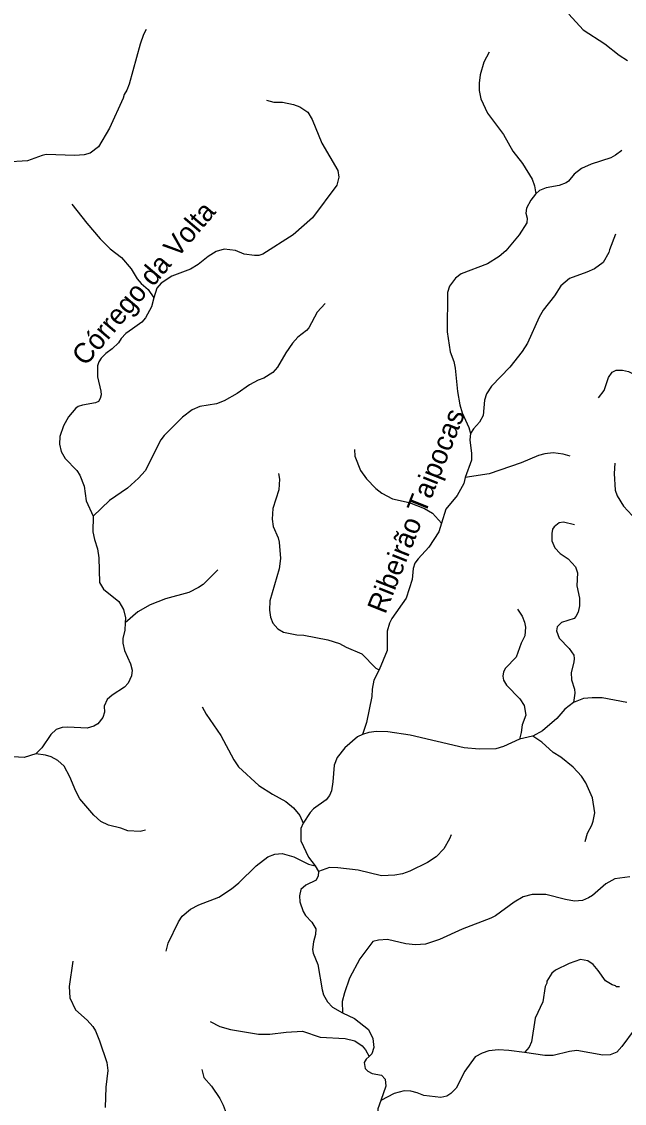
# Model space of a CAD drawing. Extents: x 500 to 555.2, y 9115.7 to 9171.
# Drawn here: x 544.2 to 549, y 9135.74 to 9144.36 of the extents above; entities that cross this region are included whole.
import ezdxf
from ezdxf.enums import TextEntityAlignment as Align

# ---------------------------------------------------------------- set-up
doc = ezdxf.new("R2010")
doc.units = 0
doc.header["$LTSCALE"] = 0.064
doc.layers.add('61', color=7, linetype='Continuous')
doc.layers.add('7', color=7, linetype='Continuous', lineweight=25)

msp = doc.modelspace()

# ---------------------------------------------------------------- linework, layer by layer
at = {"layer": '7'}
for points in [[(548.5564, 9144.4223), (548.6691, 9144.2983), (548.8429, 9144.1866), (548.9572, 9144.0957), (549.0224, 9144.0519)], [(545.189, 9144.3008), (545.1685, 9144.2602), (545.1419, 9144.1825), (545.0528, 9143.8636), (545.0338, 9143.8164), (545.0126, 9143.7827), (545.0063, 9143.7519), (544.8974, 9143.514), (544.8082, 9143.3648), (544.7427, 9143.3133), (544.6949, 9143.3013), (544.6201, 9143.2948), (544.3931, 9143.303), (544.3598, 9143.2963), (544.2439, 9143.2531), (544.0717, 9143.2422)], [(547.9205, 9144.1193), (547.8792, 9144.039), (547.8506, 9143.9389), (547.8421, 9143.8721), (547.8421, 9143.8125), (547.8553, 9143.7469), (547.908, 9143.6337), (548.0355, 9143.4636), (548.1114, 9143.3303), (548.186, 9143.233), (548.2652, 9143.106), (548.2829, 9143.0533), (548.2921, 9142.9904)], [(546.1464, 9143.7355), (546.2072, 9143.7212), (546.2755, 9143.7195), (546.3636, 9143.7032), (546.4138, 9143.6831), (546.4777, 9143.6404), (546.512, 9143.5826), (546.589, 9143.3944), (546.7167, 9143.1749), (546.7244, 9143.1241), (546.7075, 9143.0601), (546.5146, 9142.7989), (546.3595, 9142.6636), (546.1181, 9142.5091), (546.0879, 9142.5), (546.0515, 9142.4977), (545.9686, 9142.5103), (545.8999, 9142.5379), (545.8104, 9142.55), (545.7468, 9142.5299), (545.6839, 9142.4897), (545.6036, 9142.427), (545.5433, 9142.3891), (545.3925, 9142.3348), (545.3089, 9142.2787), (545.2745, 9142.2387), (545.2514, 9142.1606)], [(548.9786, 9143.3359), (548.9286, 9143.2976), (548.8912, 9143.2772), (548.7338, 9143.2277), (548.6578, 9143.1932), (548.5974, 9143.148), (548.5526, 9143.0918), (548.5337, 9143.0781), (548.4795, 9143.0567), (548.3757, 9143.0389), (548.3222, 9143.0154), (548.2921, 9142.9904)], [(548.2921, 9142.9904), (548.29, 9142.9887), (548.2522, 9142.9404), (548.2195, 9142.8754), (548.2128, 9142.836), (548.2241, 9142.796), (548.2208, 9142.759), (548.1602, 9142.6626), (548.0552, 9142.5353), (548, 9142.4897), (547.9082, 9142.4323), (547.6981, 9142.3523), (547.6524, 9142.3177), (547.6046, 9142.2553), (547.5896, 9142.203), (547.5858, 9141.8898), (547.6121, 9141.7313), (547.6395, 9141.6535), (547.6515, 9141.6), (547.6698, 9141.4149), (547.6884, 9141.3075), (547.7068, 9141.246), (547.759, 9141.1286), (547.7738, 9141.0809)], [(544.5978, 9142.9089), (544.7152, 9142.7564), (544.8221, 9142.6304), (544.9016, 9142.551), (544.9917, 9142.4823), (545.0704, 9142.3927), (545.1183, 9142.3127), (545.1492, 9142.2757), (545.2044, 9142.2268), (545.2514, 9142.1606)], [(548.9291, 9142.6689), (548.8789, 9142.544), (548.8751, 9142.5233), (548.83, 9142.4441), (548.7616, 9142.3924), (548.6999, 9142.3647), (548.5621, 9142.3154), (548.4924, 9142.2574), (548.4423, 9142.1777), (548.3524, 9142.0626), (548.3212, 9142.0076), (548.2273, 9141.8008), (548.1856, 9141.7343), (548.0864, 9141.6086), (547.9393, 9141.458), (547.8998, 9141.3973), (547.8846, 9141.3454), (547.8731, 9141.2238), (547.8449, 9141.1701), (547.7964, 9141.1167), (547.7738, 9141.0809)], [(545.2514, 9142.1606), (545.2305, 9142.0897), (545.1847, 9142.001), (545.1551, 9141.9681), (545.0793, 9141.9153), (545.0262, 9141.8781), (544.9895, 9141.8369), (544.9678, 9141.8033), (544.9178, 9141.755), (544.8671, 9141.719), (544.8293, 9141.6795), (544.8127, 9141.6517), (544.8022, 9141.619), (544.8012, 9141.5324), (544.8287, 9141.4182), (544.8303, 9141.3888), (544.8233, 9141.3588), (544.8091, 9141.3354), (544.7865, 9141.3244), (544.6806, 9141.3064), (544.6477, 9141.2955), (544.6276, 9141.2808), (544.5712, 9141.212), (544.5309, 9141.1401), (544.5014, 9141.0567), (544.4992, 9140.9951), (544.5108, 9140.9356), (544.5434, 9140.8818), (544.6359, 9140.7862), (544.6598, 9140.749), (544.694, 9140.6611), (544.7105, 9140.543), (544.768, 9140.4223), (544.768, 9140.4205)], [(546.6153, 9142.1156), (546.5519, 9142.0459), (546.4862, 9141.9224), (546.467, 9141.9002), (546.3974, 9141.8483), (546.3555, 9141.8004), (546.3005, 9141.722), (546.2364, 9141.6089), (546.1976, 9141.5651), (546.1262, 9141.5216), (546.0805, 9141.5044), (546.0119, 9141.4677), (545.9134, 9141.3988), (545.8117, 9141.3405), (545.75, 9141.3164), (545.6175, 9141.2961), (545.5566, 9141.2701), (545.4789, 9141.2116), (545.3312, 9141.0644), (545.3054, 9141.0307), (545.1804, 9140.7839), (545.1278, 9140.7233), (545.0415, 9140.6452), (544.8973, 9140.5468), (544.768, 9140.4205)], [(548.7933, 9141.3636), (548.8368, 9141.423), (548.8724, 9141.5271), (548.9023, 9141.5694), (548.9324, 9141.5836), (548.9842, 9141.5836), (549.0312, 9141.5738), (549.1401, 9141.5213), (549.1892, 9141.5032), (549.238, 9141.474), (549.3757, 9141.4132), (549.4713, 9141.35), (549.5639, 9141.3059), (549.8091, 9141.2538), (549.864, 9141.225), (549.9093, 9141.1821)], [(547.7738, 9141.0809), (547.7682, 9141.0296), (547.7812, 9140.921), (547.7813, 9140.8678), (547.7316, 9140.7287)], [(546.8493, 9140.9539), (546.8514, 9140.8994), (546.8953, 9140.7857), (546.9444, 9140.7199), (547.0181, 9140.6409), (547.0672, 9140.6034), (547.1509, 9140.5607), (547.2853, 9140.5292), (547.4068, 9140.4835), (547.4714, 9140.4446), (547.5424, 9140.3656)], [(548.5671, 9140.8991), (548.5102, 9140.9162), (548.4321, 9140.926), (548.3647, 9140.9178), (548.3139, 9140.9051), (548.1761, 9140.8456), (547.9225, 9140.7591), (547.7316, 9140.7287)], [(548.9218, 9140.8426), (548.9181, 9140.7609), (548.9266, 9140.6297), (548.9425, 9140.5823), (548.9922, 9140.5014), (549.0611, 9140.427), (549.1211, 9140.3318), (549.161, 9140.285), (549.2336, 9140.2502), (549.4433, 9140.2095), (549.612, 9140.2223), (549.6545, 9140.2159), (549.6966, 9140.1965), (549.718, 9140.1735), (549.7331, 9140.1163)], [(546.2439, 9140.7613), (546.2509, 9140.7168), (546.2461, 9140.6322), (546.1983, 9140.4826), (546.1936, 9140.3985), (546.2002, 9140.3395), (546.2408, 9140.2476), (546.249, 9140.2148), (546.2591, 9140.083), (546.249, 9140.0005), (546.1756, 9139.7479), (546.1723, 9139.6725), (546.1803, 9139.6178), (546.1993, 9139.5696), (546.2391, 9139.5231), (546.2833, 9139.4972), (546.3886, 9139.4766), (546.4455, 9139.4728), (546.6358, 9139.4369), (546.7287, 9139.4069), (546.7812, 9139.3774), (546.9064, 9139.3245), (547.0175, 9139.2114), (547.0459, 9139.1959)], [(547.7316, 9140.7287), (547.7199, 9140.6823), (547.6669, 9140.5855), (547.5773, 9140.477), (547.5424, 9140.3656)], [(544.768, 9140.4205), (544.7655, 9140.2958), (544.7762, 9140.2346), (544.8009, 9140.1617), (544.8123, 9140.0896), (544.8174, 9139.8919), (544.8482, 9139.8409), (544.9714, 9139.7401), (545.0097, 9139.6778), (545.0236, 9139.6123), (545.0217, 9139.5703)], [(547.5424, 9140.3656), (547.521, 9140.2974), (547.4397, 9140.1744), (547.3553, 9140.0818), (547.3307, 9140.0458), (547.3151, 9140.005), (547.3089, 9139.9158), (547.2612, 9139.7682), (547.147, 9139.6046), (547.1279, 9139.5697), (547.1088, 9139.505), (547.1087, 9139.3515), (547.0459, 9139.1959)], [(548.6011, 9140.3533), (548.5135, 9140.3748), (548.4779, 9140.3672), (548.4386, 9140.3364), (548.4272, 9140.3179), (548.4195, 9140.2831), (548.4214, 9140.2253), (548.446, 9140.1678), (548.4881, 9140.1241), (548.5505, 9140.0811), (548.6081, 9140.0183), (548.6261, 9139.9702), (548.6212, 9139.8665), (548.6409, 9139.7673), (548.6408, 9139.7057), (548.6295, 9139.6571), (548.6125, 9139.6216), (548.5989, 9139.607), (548.4967, 9139.5743), (548.464, 9139.5403), (548.4571, 9139.507), (548.4788, 9139.4499), (548.5601, 9139.3667), (548.5952, 9139.3133), (548.5984, 9139.2859), (548.5965, 9139.257), (548.5737, 9139.1743), (548.5766, 9139.1178), (548.6013, 9139.0431), (548.6047, 9139.0109), (548.5924, 9138.9376)], [(545.7592, 9139.9928), (545.6431, 9139.8771), (545.6071, 9139.8516), (545.5303, 9139.814), (545.3424, 9139.7631), (545.2208, 9139.7145), (545.1228, 9139.6589), (545.0217, 9139.5703)], [(548.1463, 9139.6815), (548.1845, 9139.6243), (548.2042, 9139.5757), (548.2111, 9139.5376), (548.2059, 9139.469), (548.1763, 9139.4093), (548.1365, 9139.299), (548.052, 9139.2104), (548.0361, 9139.182), (548.0292, 9139.146), (548.0346, 9139.1139), (548.0604, 9139.0746), (548.1667, 9138.966), (548.2002, 9138.9115), (548.2127, 9138.8366), (548.1833, 9138.7586), (548.1768, 9138.6964), (548.1622, 9138.6455)], [(545.0217, 9139.5703), (545.019, 9139.5127), (545.0044, 9139.4463), (545.0044, 9139.4099), (545.0173, 9139.352), (545.0647, 9139.2438), (545.0765, 9139.1934), (545.0715, 9139.1481), (545.0456, 9139.0896), (545.0162, 9139.0583), (544.9195, 9138.9959), (544.8797, 9138.961), (544.8554, 9138.9067), (544.8566, 9138.8595), (544.8438, 9138.8174), (544.8048, 9138.7677), (544.7725, 9138.7477), (544.7178, 9138.7331), (544.5663, 9138.7412), (544.5205, 9138.7378), (544.4711, 9138.7203), (544.4286, 9138.6812), (544.3567, 9138.5762), (544.3112, 9138.5267), (544.3105, 9138.5265)], [(547.0459, 9139.1959), (547.0016, 9139.1142), (546.989, 9139.0425), (546.9857, 9138.9834), (546.9431, 9138.7773), (546.913, 9138.6824)], [(548.5924, 9138.9376), (548.5247, 9138.8842), (548.4609, 9138.809), (548.3475, 9138.7109), (548.2685, 9138.6684)], [(549.0185, 9138.9355), (549.0183, 9138.9355), (548.8206, 9138.9741), (548.7422, 9138.9743), (548.6736, 9138.9675), (548.5924, 9138.9376)], [(545.6339, 9138.9025), (545.667, 9138.8436), (545.7847, 9138.6729), (545.8885, 9138.4789), (545.9234, 9138.4238), (546.0858, 9138.2751), (546.1957, 9138.2063), (546.3006, 9138.1488), (546.3637, 9138.097), (546.4138, 9138.0361), (546.441, 9137.9754)], [(544.3105, 9138.5265), (544.216, 9138.4971), (544.0824, 9138.505), (543.8282, 9138.4936), (543.6215, 9138.4657), (543.5553, 9138.4708), (543.4868, 9138.493), (543.4412, 9138.5215), (543.388, 9138.5762), (543.3692, 9138.621), (543.3605, 9138.6763), (543.3283, 9138.7439), (543.3049, 9138.7773), (543.2328, 9138.8495)], [(546.913, 9138.6824), (546.8722, 9138.6637), (546.7714, 9138.5761), (546.7103, 9138.4985), (546.6857, 9138.4378), (546.6772, 9138.3034), (546.666, 9138.2335), (546.6507, 9138.1962), (546.6232, 9138.1607), (546.5217, 9138.09), (546.4946, 9138.0599), (546.441, 9137.9754)], [(548.1622, 9138.6455), (548.0347, 9138.586), (547.9756, 9138.5675), (547.843, 9138.5642), (547.7223, 9138.5757), (547.2932, 9138.6755), (547.1136, 9138.7034), (547.0235, 9138.7051), (546.9617, 9138.6969), (546.913, 9138.6824)], [(548.2685, 9138.6684), (548.2668, 9138.6675), (548.1622, 9138.6455)], [(548.6876, 9137.8292), (548.7037, 9137.8961), (548.7389, 9137.96), (548.7503, 9137.9921), (548.7621, 9138.0577), (548.7458, 9138.177), (548.6929, 9138.2956), (548.6563, 9138.3482), (548.5899, 9138.4199), (548.4924, 9138.5016), (548.4309, 9138.5379), (548.3419, 9138.6205), (548.2685, 9138.6684)], [(545.185, 9137.9193), (545.1426, 9137.908), (545.0421, 9137.9146), (544.9874, 9137.9348), (544.8898, 9137.9582), (544.8275, 9137.9875), (544.7725, 9138.0399), (544.6614, 9138.168), (544.6284, 9138.23), (544.5822, 9138.3454), (544.5363, 9138.43), (544.486, 9138.4755), (544.4335, 9138.5034), (544.387, 9138.5178), (544.3105, 9138.5265)], [(546.441, 9137.9754), (546.4209, 9137.9327), (546.4205, 9137.833)], [(546.4205, 9137.833), (546.4836, 9137.7035), (546.5352, 9137.6338), (546.5623, 9137.5895)], [(547.6192, 9137.882), (547.6066, 9137.8501), (547.5601, 9137.7708), (547.5003, 9137.7076), (547.4308, 9137.6607), (547.2898, 9137.5917), (547.2308, 9137.572), (547.169, 9137.5617), (547.0645, 9137.5554), (546.8771, 9137.5994), (546.7151, 9137.6193), (546.6503, 9137.6204), (546.5623, 9137.5895)], [(545.3495, 9136.9558), (545.3636, 9137.019), (545.4464, 9137.1881), (545.4771, 9137.2326), (545.5428, 9137.2899), (545.6081, 9137.3233), (545.7686, 9137.3864), (545.8683, 9137.4517), (545.9272, 9137.5006), (546.065, 9137.6353), (546.1575, 9137.7078), (546.2132, 9137.7275), (546.2722, 9137.7324), (546.3655, 9137.7073), (546.4817, 9137.6492), (546.5352, 9137.6338)], [(546.5623, 9137.5895), (546.5593, 9137.5561), (546.5433, 9137.5198), (546.462, 9137.4795), (546.4221, 9137.4458), (546.4117, 9137.3962), (546.4137, 9137.3491), (546.4387, 9137.2703), (546.4576, 9137.24), (546.5088, 9137.1858), (546.541, 9137.1338), (546.538, 9137.0885), (546.5216, 9137.0288), (546.5152, 9136.9691), (546.5202, 9136.9396), (546.5566, 9136.8491), (546.5903, 9136.6457), (546.6026, 9136.6059), (546.6344, 9136.5504), (546.6732, 9136.5087), (546.7532, 9136.4622)], [(549.0416, 9137.546), (548.9223, 9137.5304), (548.8509, 9137.4913), (548.7458, 9137.3996), (548.7136, 9137.3786), (548.6663, 9137.3585), (548.6019, 9137.354), (548.5293, 9137.3667), (548.3725, 9137.4058), (548.2635, 9137.4076), (548.1929, 9137.3868), (548.1198, 9137.3457), (547.9722, 9137.2376), (547.9351, 9137.2188), (547.7052, 9137.1301), (547.5248, 9137.0466), (547.4155, 9137.0112), (547.3344, 9137.0059), (547.2571, 9137.0123), (547.1115, 9137.0468), (547.0406, 9137.0435), (546.9935, 9137.0307), (546.8919, 9136.8937), (546.809, 9136.7407), (546.7688, 9136.6238), (546.7516, 9136.5547), (546.7532, 9136.4622)], [(544.6036, 9136.8745), (544.5746, 9136.6745), (544.5814, 9136.5821), (544.6267, 9136.4881), (544.7201, 9136.4043), (544.7636, 9136.3541), (544.7848, 9136.3197), (544.8185, 9136.2394), (544.8766, 9136.0678), (544.8829, 9136.0047), (544.8682, 9135.872), (544.8614, 9135.7095)], [(548.9597, 9136.6697), (548.9351, 9136.6712), (548.9271, 9136.6793), (548.9006, 9136.6859), (548.8479, 9136.719), (548.7909, 9136.8003), (548.75, 9136.8473), (548.707, 9136.8775), (548.6499, 9136.8878), (548.5588, 9136.8565), (548.4494, 9136.8028), (548.4206, 9136.7802), (548.3802, 9136.7154), (548.3797, 9136.7004), (548.3677, 9136.6721), (548.3481, 9136.5512), (548.2868, 9136.4208), (548.2601, 9136.2318), (548.2392, 9136.1895), (548.2025, 9136.1465)], [(546.7532, 9136.4622), (546.8475, 9136.4195), (546.961, 9136.3315), (546.9955, 9136.2579), (547.0037, 9136.1864), (546.9866, 9136.1373), (546.9654, 9136.1167)], [(545.6987, 9136.3932), (545.7764, 9136.355), (545.8609, 9136.3312), (546.0852, 9136.2928), (546.1751, 9136.294), (546.3045, 9136.3103), (546.4341, 9136.317), (546.5741, 9136.2698), (546.7748, 9136.2593), (546.8523, 9136.24), (546.911, 9136.2011), (546.9375, 9136.1688), (546.9654, 9136.1167)], [(549.0755, 9136.3284), (548.9783, 9136.195), (548.9376, 9136.1496), (548.8863, 9136.1284), (548.8272, 9136.1267), (548.6205, 9136.1627), (548.5621, 9136.1561), (548.4316, 9136.1235), (548.3646, 9136.1234), (548.2025, 9136.1465)], [(546.9654, 9136.1167), (546.9417, 9136.0936), (546.9251, 9136.0672), (546.9326, 9136.0191), (546.9542, 9135.9973), (546.9902, 9135.9811), (547.0632, 9135.9669), (547.0924, 9135.9354), (547.0989, 9135.8802), (547.0585, 9135.765)], [(548.2025, 9136.1465), (548.078, 9136.1643), (547.9954, 9136.1691), (547.9185, 9136.1609), (547.8653, 9136.1424), (547.8112, 9136.1117), (547.7286, 9135.9977), (547.6583, 9135.8643), (547.6161, 9135.8204), (547.5838, 9135.8001), (547.5353, 9135.7888), (547.4008, 9135.8052), (547.3483, 9135.8265), (547.2972, 9135.8393), (547.2433, 9135.8412), (547.1647, 9135.8199), (547.0585, 9135.765)], [(545.6332, 9136.0119), (545.6486, 9135.9473), (545.7096, 9135.8789), (545.7765, 9135.7795), (545.8038, 9135.7278), (545.8353, 9135.6434), (545.8458, 9135.5899), (545.8393, 9135.2842), (545.8601, 9135.2112), (545.8765, 9135.1778), (545.9042, 9135.1431), (545.9846, 9135.0759)], [(547.0585, 9135.765), (547.0351, 9135.6983), (547.0351, 9135.6051), (547.0593, 9135.517), (547.0595, 9135.4734), (546.9858, 9135.3065), (546.9793, 9135.2489), (546.984, 9135.1878), (546.9775, 9135.1449), (546.9642, 9135.1198), (546.8839, 9135.0392), (546.8312, 9134.9976), (546.8118, 9134.9714), (546.7937, 9134.886)]]:
    msp.add_lwpolyline(points, dxfattribs=at)

# ---------------------------------------------------------------- texts
at = {"layer": '61'}
for s, rotation, p in [('Córrego da Volta', 49.686, (545.2283, 9142.2265)), ('Ribeirão Taipocas', 68.319, (547.4125, 9140.4357))]:
    msp.add_text(s, height=0.16, rotation=rotation, dxfattribs=at).set_placement(p, align=Align.CENTER)

doc.saveas('drawing.dxf')
